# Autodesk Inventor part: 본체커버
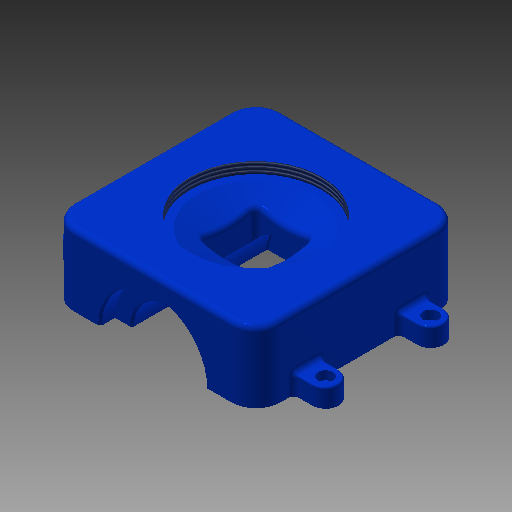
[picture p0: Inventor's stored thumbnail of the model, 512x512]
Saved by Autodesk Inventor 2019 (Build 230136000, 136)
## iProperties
Created: 2018-01
Part Number: 본체커버
Material: 알루미늄 6061
Document SubType Name: Modeling
Designer: mduedu
Density: 1 g/cm^3
Appearance: 선명 - 파란색
Author: mduedu
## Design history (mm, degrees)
sketch "스케치1"
  geometry: L1 (55, 55)-(-55, 55); L2 (-55, 55)-(-55, -55); L3 (-55, -55)-(55, -55); L4 (55, -55)-(55, 55); L5 (55, 55)-(-55, -55); L6 (-55, 55)-(55, -55); 1 further point
  constraints: 12 end point, 2 midpoint, 2 parallel, 1 horizontal, 1 perpendicular
  dimensions: "d0" = 110 distance of L3.end L2.end; "d1" = 110 distance of L2.end L1.end
extrude "돌출1" new body sketch "스케치1" distance "d2" = 38; taper "d3" = 0 deg
revolve "회전1" stored, may be unused: angle "d13" = 90 deg
fillet "모깎기1" dims "d14" = 1
fillet "모깎기2" dims "d15" = 13
fillet "모깎기3" dims "d16" = 3
sketch "스케치3"
  geometry: L1 (-15, -15)-(15, -15); L2 (15, -15)-(15, 15); L3 (15, 15)-(-15, 15); L4 (-15, 15)-(-15, -15); L5 (42, 55)-(-42, 55) reference; L6 (-15, -15)-(15, 15); L7 (15, -15)-(-15, 15); 2 further points
  constraints: 12 end point, 2 parallel, 1 horizontal, 1 midpoint, 1 perpendicular, 1 vertical alignment
  dimensions: "d19" = 30 distance of L3.end L1.start; "d20" = 30 distance between parallel lines of L2 L4; "d65" = 40 distance between parallel lines of L5 L3
extrude "돌출2" cut sketch "스케치3" extent not by distance; stored distance "d21" = 38; taper "d22" = 0 deg
fillet "모깎기4" dims "d23" = 3
sketch "스케치4"
  geometry: L1 (38, 35)-(32, 35); L2 (32, 35)-(32, 31); L3 (32, 31)-(25, 15); L4 (25, 15)-(25, 0); L5 (25, 0)-(38, 0); L6 (38, 0)-(38, 35); L7 (38, 42)-(38, -42) reference; 1 further point
  constraints: 12 end point, 2 parallel, 1 collinear, 1 horizontal, 1 horizontal alignment, 1 perpendicular
  dimensions: "d24" = 6 distance of L1.start L1.end; "d26" = 70 diameter of L1 L5; "d28" = 62 diameter of L2.end L5; "d29" = 30 diameter of L3.end L5; "d30" = 7 horizontal distance of L2.end L3.end
revolve "회전2" sketch "스케치4" stored, may be unused: angle "d31" = 90 deg
feature "스레드1" dims "d74" = 10, "d75" = 0
chamfer "모따기2" distance "d36" = 1; stored, may be unused: second distance "d37" = 2, angle "d38" = 45 deg
sketch "스케치5"
  geometry: L1 (-42, 55)-(-29, 55) reference; L2 (-55, -42)-(-55, 42) reference; L3 (42, -55)-(-42, -55) reference; L4 (55, 42)-(55, -42) reference; L5 (55, 35)-(65, 35); L6 (65, 21)-(55, 21); L7 (55, 21)-(55, 35); L8 (55, 42)-(55, -42) reference; L9 (28, 54)-(28, 47) reference; L10 (28, 47)-(20, 47) reference; L11 (19, 46)-(19, -24) reference; L12 (18, -25)-(7.5, -25) reference; L13 (7.5, -25)-(5.479, -28.5) reference; L14 (4.613, -29)-(-4.613, -29) reference; L15 (-5.479, -28.5)-(-7.5, -25) reference; L16 (-7.5, -25)-(-18, -25) reference; L17 (-19, -24)-(-19, 46) reference; L18 (-20, 47)-(-28, 47) reference; L19 (-28, 47)-(-28, 54) reference; L20 (19, 46)-(20, 47) reference; L21 (-20, 47)-(-19, 46) reference; L22 (-29, 55)-(-28, 54) reference; L23 (29, 55)-(42, 55) reference; L24 (28, 54)-(29, 55) reference; A1 r 13 centre (-42, 42) between (-42, 55) and (-55, 42) reference; A2 r 13 centre (-42, -42) between (-55, -42) and (-42, -55) reference; A3 r 13 centre (42, -42) between (42, -55) and (55, -42) reference; A4 r 13 centre (42, 42) between (55, 42) and (42, 55) reference; A5 r 7 centre (65, 28) between (65, 21) and (65, 35); A6 r 1 centre (18, -24) between (18, -25) and (19, -24) reference; A7 r 1 centre (4.613, -28) between (4.613, -29) and (5.479, -28.5) reference; A8 r 1 centre (-4.613, -28) between (-5.479, -28.5) and (-4.613, -29) reference; A9 r 1 centre (-18, -24) between (-19, -24) and (-18, -25) reference; 1 further point
  constraints: 6 end point, 2 point on circle, 2 tangent, 1 centre point, 1 collinear, 1 horizontal, 1 parallel, 1 point on line
  dimensions: "d39" = 14 distance between parallel lines of L6 L5; "d41" = 28 vertical distance of A5.centre point (0, 0); "d42" = 10 distance from line of A5.centre L4
extrude "돌출3" join sketch "스케치5" distance "d43" = 10; taper "d44" = 0 deg
fillet "모깎기6" dims "d45" = 1
fillet "모깎기7" dims "d46" = 3
sketch "스케치6"
  geometry: A1 r 7 centre (-65, 28) between (-65, 35) and (-65, 21) reference; A2 r 7 centre (-65, -28) between (-65, -21) and (-65, -35) reference; A3 r 7 centre (65, -28) between (65, -35) and (65, -21) reference; A4 r 7 centre (65, 28) between (65, 21) and (65, 35) reference; 5 further points
  constraints: 4 coincident
sketch "스케치7"
  geometry: 4 further points
  constraints: 4 other
hole "구멍1" sketch "스케치7" at (-65, 28), (65, 28), (-65, -28), (65, -28) diameter "d47" = 4.5; stored, may be unused: countersink angle "d51" = 90 deg, drill point angle "d53" = 0 deg; dims "d48" = 6, "d49" = 8, "d50" = 4.6, "d52" = 8
sketch "스케치9" dims "d66" = 46
  geometry: 3 further points
  constraints: 2 vertical alignment, 1 coincident, 2 other
hole "구멍2" sketch "스케치9" at (0, 23) diameter "d67" = 3.242; stored, may be unused: countersink angle "d71" = 90 deg, drill point angle "d73" = 118 deg; dims "d68" = 9, "d69" = 4, "d70" = 2, "d72" = 11
sketch "스케치8"
  geometry: L1 (-97, 35)-(-97, 0) reference; L2 (0, 38)-(-84, 38) reference; 2 further points
  constraints: 1 other
  dimensions: "d54" = 55 distance from line of point (-42, 23) L1; "d55" = 15 distance from line of point (-42, 23) L2
feature "엠보싱1" sketch "스케치8" dims "d0" = 110, "d1" = 110, "d56" = 0.5, "d57" = 0
node "솔리드1"
mirror "대칭1"
mirror "대칭2"
sketch "스케치2"
  geometry: L1 (-55, 55)-(55, 55) reference; L2 (-55, -55)-(-55, 55) reference; L3 (55, -55)-(-55, -55) reference; L4 (55, 55)-(55, -55) reference; L5 (0, 55)-(28, 55); L6 (19, 47)-(19, -25); L7 (19, -25)-(7.5, -25); L8 (0, -25.854)-(0, 55); L9 (7.5, -25)-(5.191, -29); L10 (5.191, -29)-(0, -29); L11 (0, -29)-(0, -25.854); L12 (19, 47)-(28, 47); L13 (28, 47)-(28, 55); 1 further point
  constraints: 18 end point, 2 horizontal, 2 perpendicular, 1 midpoint, 1 parallel, 1 point on line, 1 vertical
  dimensions: "d7" = 38 diameter of L6 L8; "d58" = 4 distance between parallel lines of L7 L10; "d59" = 30 deg angle of L8 L9; "d60" = 15 diameter of L7.end L8; "d61" = 56 diameter of L13 L8; "d62" = 8 distance of L12.end L5.end; "d63" = 84 distance between parallel lines of L10 L5
node "투영된 루프1"
node "투영된 루프2"
